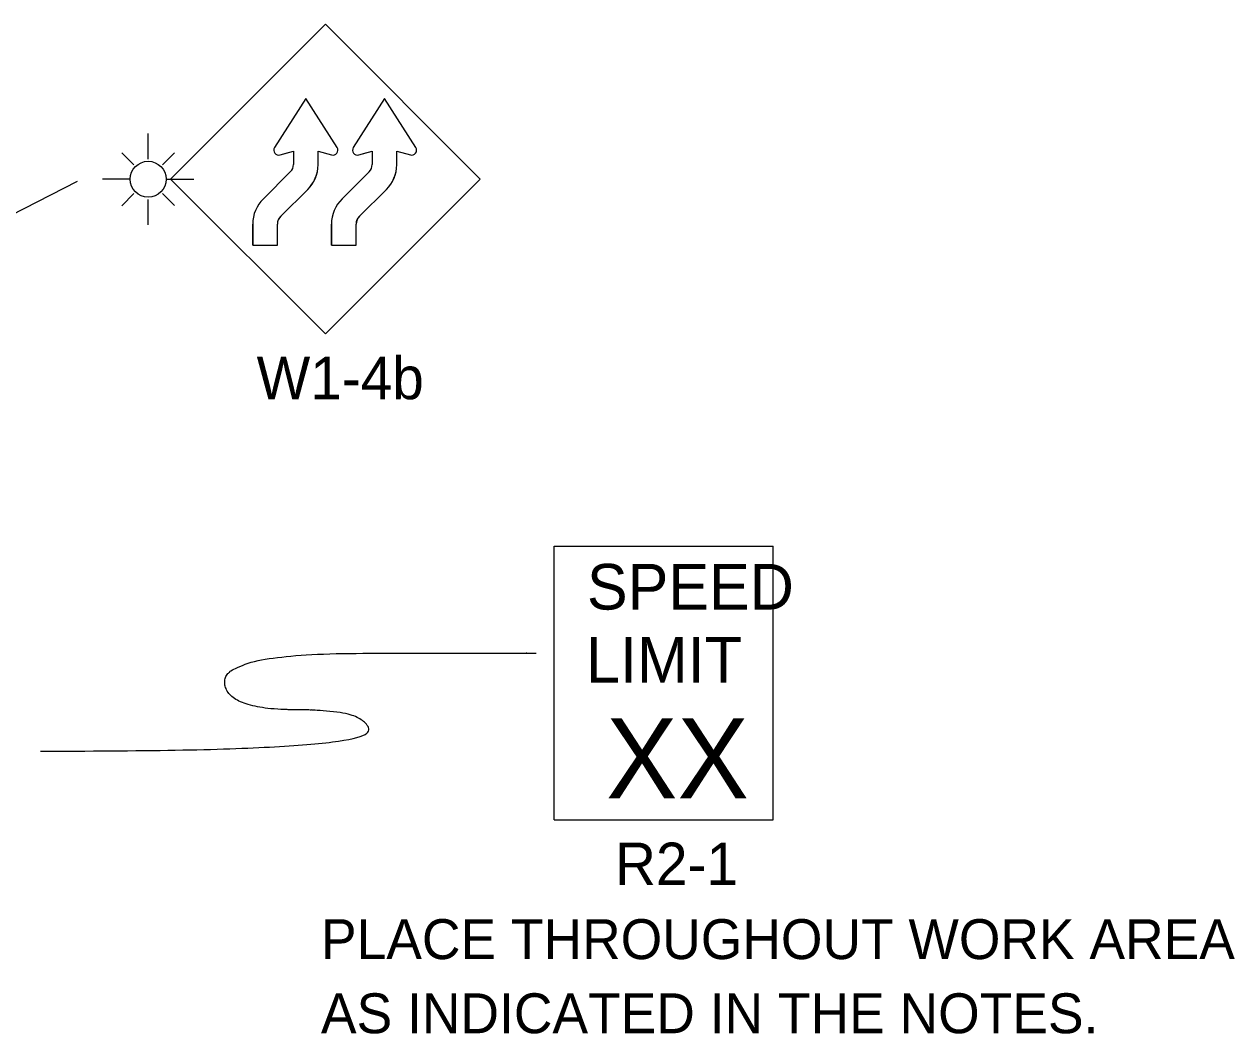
# Model space of a CAD drawing. Extents: x 16544 to 19504, y 5662 to 6909.
# Drawn here: x 17209.8 to 17422, y 6359.6 to 6536.6 of the extents above; entities that cross this region are included whole.
import ezdxf

# ---------------------------------------------------------------- set-up
doc = ezdxf.new("R2010")
doc.units = 0
doc.layers.add('TRAFFIC_SIGNS_PR', color=7, linetype='Continuous')
doc.layers.add('TYPICAL_TEXT_DIMEN_PR', color=7, linetype='Continuous')

msp = doc.modelspace()

# ---------------------------------------------------------------- linework, layer by layer
at = {"layer": 'TRAFFIC_SIGNS_PR'}
for p, q in [((17262.6, 6536.64), (17235.45, 6509.49)), ((17289.75, 6509.49), (17262.6, 6536.64)), ((17231.53, 6513.01), (17231.53, 6517.51)), ((17229.02, 6511.97), (17226.91, 6514.08)), ((17234.04, 6511.97), (17236.15, 6514.08)), ((17251.73, 6506.03), (17256.45, 6510.74)), ((17256.45, 6510.74), (17251.73, 6506.03)), ((17265.53, 6506.03), (17270.24, 6510.74)), ((17270.24, 6510.74), (17265.53, 6506.03)), ((17228.37, 6509.46), (17223.54, 6509.46)), ((17234.68, 6509.46), (17239.56, 6509.46)), ((17235.45, 6509.49), (17262.6, 6482.34)), ((17254.78, 6502.97), (17259.5, 6507.69)), ((17254.79, 6502.97), (17259.5, 6507.69)), ((17262.6, 6482.34), (17289.75, 6509.49)), ((17268.58, 6502.97), (17273.3, 6507.69)), ((17268.58, 6502.97), (17273.3, 6507.69)), ((17229.01, 6506.94), (17226.91, 6504.83)), ((17231.53, 6501.49), (17231.53, 6505.9)), ((17234.04, 6506.94), (17236.15, 6504.84)), ((17249.87, 6497.91), (17249.87, 6501.61)), ((17254.18, 6497.91), (17254.18, 6501.61)), ((17263.66, 6497.91), (17263.66, 6501.61)), ((17267.98, 6497.91), (17267.98, 6501.61)), ((17249.87, 6497.91), (17254.18, 6497.91)), ((17263.66, 6497.91), (17267.98, 6497.91)), ((17302.67, 6445.16), (17341.07, 6445.16)), ((17302.67, 6397.16), (17302.67, 6445.16)), ((17341.07, 6397.16), (17341.07, 6445.16)), ((17302.67, 6397.16), (17341.07, 6397.16))]:
    msp.add_line(p, q, dxfattribs=at)
for points in [[(17264.65, 6515.02), (17259.17, 6523.63), (17253.69, 6515.01)], [(17264.65, 6515.01), (17259.17, 6523.63), (17253.69, 6515.01)], [(17278.45, 6515.02), (17272.97, 6523.63), (17267.49, 6515.01)], [(17278.45, 6515.01), (17272.97, 6523.63), (17267.49, 6515.01)], [(17254.65, 6513.72), (17257.01, 6514.37), (17257.01, 6512.07)], [(17254.65, 6513.72), (17255.48, 6513.95), (17257.01, 6514.37), (17257.01, 6512.07)], [(17261.32, 6512), (17261.33, 6514.37), (17263.69, 6513.72)], [(17261.32, 6512), (17261.33, 6514.37), (17263.69, 6513.72)], [(17268.45, 6513.72), (17270.81, 6514.37), (17270.8, 6512.07)], [(17268.45, 6513.72), (17269.28, 6513.95), (17270.81, 6514.37), (17270.8, 6512.07)], [(17275.12, 6512), (17275.12, 6514.37), (17277.49, 6513.72)], [(17275.12, 6512), (17275.12, 6514.37), (17277.49, 6513.72)], [(17249.87, 6501.61), (17249.87, 6497.91), (17254.18, 6497.91), (17254.18, 6501.61)], [(17263.66, 6501.61), (17263.66, 6497.91), (17267.98, 6497.91), (17267.98, 6501.61)]]:
    msp.add_lwpolyline(points, dxfattribs=at)
msp.add_circle((17231.53, 6509.46), 3.15, dxfattribs=at)
for centre, radius, start, end in [((17254.42, 6514.55), 0.866, 147.5288, 285.3852), ((17254.42, 6514.55), 0.864, 147.5204, 285.3986), ((17263.92, 6514.55), 0.866, 254.6828, 32.2708), ((17263.92, 6514.55), 0.866, 254.6799, 32.2804), ((17273.76, 6520.81), 10.8, 212.4569, 212.4665), ((17268.22, 6514.55), 0.864, 147.5204, 285.3986), ((17268.22, 6514.55), 0.866, 147.5288, 285.3852), ((17277.72, 6514.55), 0.866, 254.6828, 32.2708), ((17277.72, 6514.55), 0.866, 254.6799, 32.2804), ((17287.56, 6520.81), 10.8, 212.4569, 212.4665), ((17255.16, 6512.07), 1.85, 314.2125, 0), ((17255.16, 6512.07), 1.85, 314.2123, 0.1238), ((17255.16, 6512.07), 6.17, 314.2125, 359.3819), ((17255.16, 6512.07), 6.17, 314.7687, 359.3755), ((17260.84, 6503.3), 10.8, 74.68, 74.6808), ((17268.95, 6512.07), 1.85, 314.2125, 0), ((17268.95, 6512.07), 1.85, 314.2123, 0.1238), ((17268.95, 6512.07), 6.17, 314.2125, 359.3819), ((17268.95, 6512.07), 6.17, 314.7687, 359.3755), ((17274.64, 6503.3), 10.8, 74.68, 74.6808), ((17256.03, 6501.61), 6.17, 134.2125, 180), ((17256.03, 6501.61), 6.17, 134.2125, 180), ((17256.03, 6501.61), 6.17, 134.2117, 180), ((17269.83, 6501.61), 6.17, 134.2125, 180), ((17269.83, 6501.61), 6.17, 134.2125, 180), ((17269.83, 6501.61), 6.17, 134.2117, 180), ((17256.03, 6501.61), 1.85, 132.372, 180), ((17256.03, 6501.61), 1.85, 134.2125, 180), ((17269.83, 6501.61), 1.85, 132.372, 180), ((17269.83, 6501.61), 1.85, 134.2125, 180)]:
    msp.add_arc(centre, radius, start, end, dxfattribs=at)
at = {"layer": 'TYPICAL_TEXT_DIMEN_PR'}
msp.add_line((17171.69, 6484.9), (17219.15, 6509.1), dxfattribs=at)
msp.add_open_spline([(17212.67, 6409.18), (17270.13, 6409.18), (17270.13, 6416.45), (17244.95, 6416.45), (17244.95, 6426.36), (17294.6, 6426.36), (17299.53, 6426.36)], degree=2, dxfattribs=at)

# ---------------------------------------------------------------- texts
at = {"layer": 'TRAFFIC_SIGNS_PR'}
for s, height, p in [('W1-4b', 7.44, (17250.55, 6470.9)), ('SPEED', 8, (17308.44, 6434.02)), ('LIMIT', 8, (17308.28, 6421.22)), ('XX', 14.031, (17311.79, 6400.92)), ('R2-1', 7.44, (17313.35, 6385.72)), ('PLACE THROUGHOUT WORK AREA', 7, (17261.82, 6372.74)), ('AS INDICATED IN THE NOTES.', 7, (17261.82, 6359.74))]:
    msp.add_text(s, height=height, dxfattribs=at).set_placement(p)

doc.saveas('drawing.dxf')
